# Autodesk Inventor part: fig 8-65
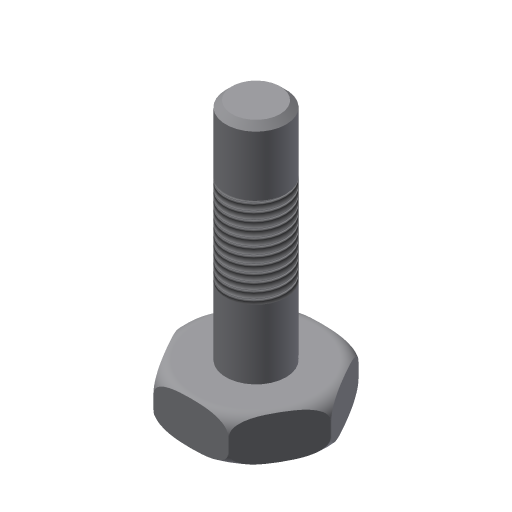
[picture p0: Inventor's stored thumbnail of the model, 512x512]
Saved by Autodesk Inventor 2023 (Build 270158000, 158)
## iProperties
Created: 2002-01
Part Number: fig 8-65
Document SubType Name: Modeling
Designer: ***
Density: 1 g/cm^3
Material: Generic
Appearance: Default
Control State: 0
Master: False
Checked Out: False
Shininess: 77.0
Length Units: 11269
Angle Units: 11279
Time Units: 11290
Mass Units: 11283
Length Display Precision: 3
Angle Display Precision: 2
Density: 0.0
Volumn: 0.0
Area: 0.0
PropertySet Name: Model Information
Author: ***
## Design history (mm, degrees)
sketch "Sketch1"
  geometry: C1 r 25 at (0, 0)
  constraints: 1 centre point
  dimensions: "d0" = 50 diameter of C1
extrude "Extrusion1" new body sketch "Sketch1" distance "d1" = 15; taper "d2" = 0 deg
fillet "Fillet1" dims "d3" = 5
sketch "Sketch2"
  geometry: L1 (25.058, 0)-(12.529, -21.701); L2 (12.529, -21.701)-(-12.529, -21.701); L3 (-12.529, -21.701)-(-25.058, 0); L4 (-25.058, 0)-(-12.529, 21.701); L5 (-12.529, 21.701)-(12.529, 21.701); L6 (12.529, 21.701)-(25.058, 0); 1 further point
  constraints: 12 end point, 11 other
extrude "Extrusion2" sketch "Sketch2" extent not by distance; stored distance "d4" = 15; taper "d5" = 0 deg
sketch "Sketch3"
  geometry: C1 r 10.044 at (0, 0); 1 further point
  constraints: 1 centre point, 1 coincident
extrude "Extrusion3" join sketch "Sketch3" distance "d6" = 75; taper "d7" = 0 deg
chamfer "Chamfer1" distance "d8" = 2; stored, may be unused: second distance "d9" = 2, angle "d16" = 45 deg
thread "Thread3" dims "d14" = 30, "d15" = 20
body "Solid1"
